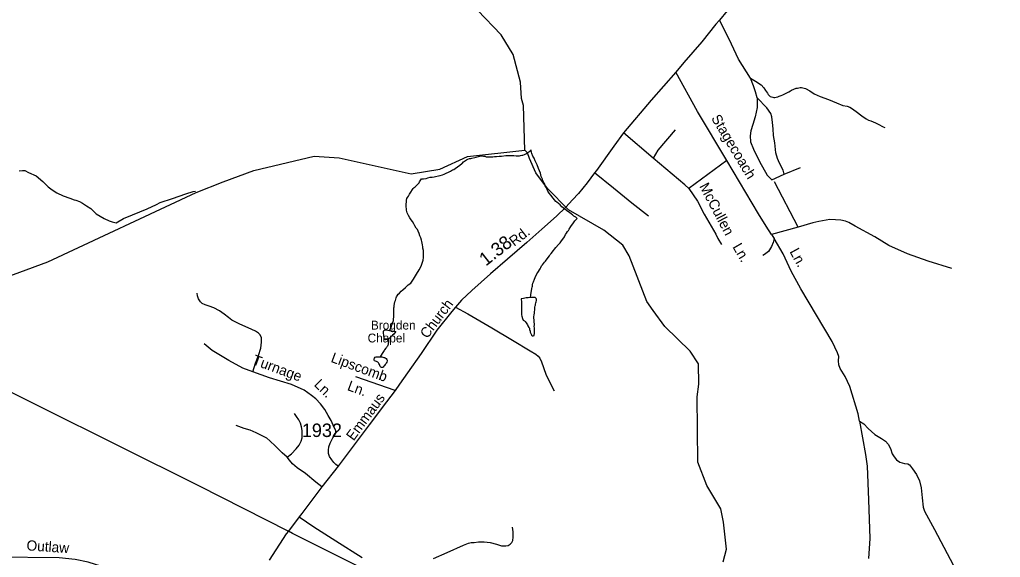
# Model space of a CAD drawing. Extents: x 2206922 to 2357709, y 510027 to 673830.
# Drawn here: x 2296847 to 2305951, y 559014 to 564008 of the extents above; entities that cross this region are included whole.
import ezdxf

# ---------------------------------------------------------------- set-up
doc = ezdxf.new("R2010")
doc.units = 0
for name, color, linetype in [('Exist Cultural Church with Cemetery Label', 7, 'Continuous'), ('Exist Hydrographic Creek Single Shore', 7, 'Continuous'), ('Exist Hydrographic Misc Water Feature', 7, 'Continuous'), ('Exist Road Non-System Type 51', 7, 'Continuous'), ('Exist Road Non-System Type 51 Label', 7, 'Continuous'), ('Exist Road Secondary Mileage Hundredths English Label', 7, 'Continuous'), ('Exist Road Secondary Type 51 Attributed', 7, 'Continuous'), ('Exist Road Secondary Type 51 Label', 7, 'Continuous'), ('Exist Road Secondary Type 51 Number Label', 7, 'Continuous'), ('Exist Utilities Electrical Transmission Line', 7, 'Continuous')]:
    doc.layers.add(name, color=color, linetype=linetype)

msp = doc.modelspace()

# ---------------------------------------------------------------- linework, layer by layer
at = {"layer": 'Exist Hydrographic Creek Single Shore'}
for points in [[(2301537, 562794.8), (2301524.1, 563211.1), (2301506, 563276), (2301497, 563426.5), (2301427.1, 563683), (2301317.2, 563865.6), (2301098.2, 564096.3)], [(2298484, 562402.3), (2298734.5, 562501.6), (2299020.8, 562606.5), (2299580, 562738.8), (2299813.1, 562725.3), (2300481, 562575.1), (2300747.1, 562618.6), (2301004.1, 562737.3), (2301537, 562794.8)], [(2303376.1, 558974), (2303409.1, 559090.1), (2303381.2, 559341.7), (2303355.2, 559465.3), (2303227, 559680), (2303142.1, 559896.5), (2303135.2, 560503.3), (2303151.2, 560622.1), (2303149.1, 560812.3), (2303072.2, 560927.3), (2302837, 561157.4), (2302727.1, 561307.2), (2302668, 561390.1), (2302505, 561813.4), (2302445.2, 561912.7), (2302269, 562053.2), (2301942.2, 562240.3), (2301748.2, 562439.2), (2301639.1, 562585.7), (2301579, 562717.8), (2301562, 562769.6), (2301537, 562794.8)]]:
    msp.add_lwpolyline(points, dxfattribs=at)
at = {"layer": 'Exist Hydrographic Misc Water Feature'}
for points in [[(2300576.1, 562528.5), (2300596, 562528.7), (2300619.6, 562532.9), (2300635.6, 562537), (2300657.5, 562543.4), (2300675.8, 562545.5), (2300694, 562547.6), (2300705.9, 562549.9), (2300735.6, 562555.9), (2300751.8, 562560.4), (2300771.5, 562566.4), (2300787.3, 562572.5), (2300799.4, 562578.8), (2300813.1, 562584.8), (2300821.6, 562588.8), (2300832.8, 562593.2), (2300847, 562601.2), (2300854.8, 562605.3), (2300864.8, 562611.5), (2300876.9, 562617.4), (2300890.7, 562623.9), (2300910.3, 562640), (2300932.3, 562656.1), (2300950.3, 562670.5), (2300954, 562672.3), (2300966.1, 562686.7), (2300976.2, 562692.5), (2300984, 562698.6), (2300995.8, 562707), (2301005.9, 562710.7), (2301021.9, 562717.3), (2301033.6, 562719.1), (2301045.5, 562721.4), (2301071.5, 562727.6), (2301083.8, 562731.8), (2301105.1, 562738), (2301117.4, 562740.2), (2301127.1, 562742.3), (2301141.2, 562742.3), (2301153.1, 562740.4), (2301165.2, 562738.6), (2301177.3, 562734.8), (2301195.8, 562732.8), (2301207.7, 562733), (2301223.5, 562733.1), (2301239.2, 562733.6), (2301253.6, 562735.5), (2301273.5, 562737.8), (2301299.3, 562739.9), (2301319.4, 562740.2), (2301361.3, 562746.8), (2301381.3, 562747), (2301399.2, 562747.2), (2301413.1, 562747.1), (2301432.8, 562745.4), (2301456.8, 562743.8), (2301473, 562741.8), (2301486.9, 562744.1), (2301497.2, 562746.2), (2301508.9, 562748.1), (2301519.1, 562750.2), (2301532.9, 562756.7), (2301545, 562760.5), (2301555, 562766.7), (2301582.7, 562784.9), (2301594.6, 562797.3)], [(2302023.2, 562162.2), (2302009, 562172), (2301991, 562183.7), (2301979.1, 562193.6), (2301968.8, 562201.6), (2301950.8, 562215.2), (2301936.6, 562225.1), (2301880, 562270.5), (2301863.8, 562286.3), (2301833.3, 562312), (2301825.3, 562320.1), (2301811.3, 562333.6), (2301799.2, 562349.6), (2301777.1, 562377.2), (2301762.5, 562397.3), (2301750.6, 562414.9), (2301744.3, 562430.8), (2301736.5, 562447), (2301726.2, 562464.8), (2301718, 562484.7), (2301709.6, 562498.5), (2301703.5, 562514.5), (2301699.4, 562526.4), (2301689.3, 562552.2), (2301681.1, 562582.3), (2301672.5, 562604.3), (2301664.1, 562626.2), (2301652, 562658), (2301641.8, 562677.8), (2301633.6, 562697.7), (2301621.5, 562721.5), (2301611, 562741.2), (2301600.8, 562763.5), (2301596.9, 562775.4), (2301594.6, 562787.1), (2301594.6, 562797.3)], [(2296842.5, 562604.5), (2296874.7, 562606.5), (2296894.6, 562606.7), (2296928.8, 562589.5), (2297000.8, 562557.9), (2297061.7, 562504.6), (2297111.8, 562455.3), (2297147.8, 562427.5), (2297192.1, 562399.7), (2297250.6, 562370.3), (2297312.9, 562351.1), (2297352.7, 562335.4), (2297367, 562331.7), (2297401.3, 562318), (2297429.2, 562304), (2297467.3, 562278.4), (2297507.3, 562252.9), (2297535.8, 562225.1), (2297558.2, 562205.5), (2297630.3, 562162.2), (2297676.5, 562140.7), (2297706.4, 562128.9), (2297742.7, 562119.4)], [(2300281.2, 561119.9), (2300294.8, 561148.3), (2300296.6, 561154.1), (2300299.1, 561158.2), (2300302.8, 561170.2), (2300304.6, 561178.4), (2300318.4, 561212.5), (2300317.9, 561228.3), (2300321.8, 561244.4), (2300321.6, 561258.2), (2300321.8, 561274.4), (2300321.4, 561290.2), (2300321.2, 561306.5), (2300321, 561320.3), (2300321, 561330.5), (2300323.1, 561340.3), (2300324.9, 561354.2), (2300330.3, 561386.3), (2300332.5, 561394.5), (2300334.4, 561400.7), (2300342.1, 561422.6), (2300346, 561432.6), (2300349.7, 561442.5), (2300359.8, 561458.9), (2300371.7, 561468.8), (2300387.5, 561485.1), (2300405.1, 561499.1), (2300428.9, 561521.4), (2300454.5, 561543.5), (2300476.7, 561561.7), (2300490.4, 561577.9), (2300504.1, 561598.1), (2300531.6, 561644.3), (2300555, 561684.5), (2300574.9, 561716.8), (2300592.1, 561775), (2300595.8, 561799.2), (2300595.6, 561819.1), (2300595.4, 561841.1), (2300595, 561863.1), (2300590.9, 561885.1), (2300589, 561898.8), (2300586.6, 561915), (2300582.3, 561930.6), (2300580.4, 561946.7), (2300576.3, 561960.7), (2300569.8, 561982.8), (2300561.8, 562000.7), (2300555.6, 562020.6), (2300545.1, 562044.5), (2300539, 562058.4), (2300528.5, 562072.1), (2300514.8, 562094.1), (2300504.5, 562109.8), (2300492, 562131.6), (2300480.3, 562147.5), (2300467.8, 562167.6), (2300455.7, 562189.3), (2300445.3, 562213.2), (2300437.3, 562239.1), (2300434.8, 562280.9), (2300434.6, 562297.2), (2300436.5, 562313.1), (2300438.1, 562331.1), (2300442.2, 562345.1), (2300447.7, 562355.2), (2300455.7, 562367.4), (2300465.4, 562387.4), (2300471.7, 562397.4), (2300500.9, 562439.6), (2300508.9, 562449.8), (2300518.9, 562456), (2300528.7, 562463.8), (2300542.5, 562480), (2300550.3, 562486.1), (2300554.2, 562492), (2300558.1, 562500.4), (2300576.1, 562528.5)], [(2295560.9, 561493.9), (2296269, 561525.5), (2296643, 561586.8), (2297108.1, 561757.8), (2298484, 562402.3)], [(2297742.7, 562119.4), (2297812.4, 562160), (2297895.9, 562194.4), (2298031.2, 562249.8), (2298116.7, 562290.5), (2298152.6, 562309), (2298264.6, 562346.5), (2298388.4, 562388.7), (2298456.5, 562411.7), (2298480.5, 562415.8)], [(2301589.3, 561427.8), (2301593.4, 561452), (2301602.4, 561511.8), (2301604, 561522.1), (2301606.1, 561532), (2301608.1, 561543.8), (2301611.8, 561560.3), (2301617.4, 561574), (2301627.4, 561598.1), (2301633.6, 561614.2), (2301648.5, 561648.4), (2301656.5, 561660.6), (2301678.3, 561694.6), (2301684.2, 561704.7), (2301692, 561721), (2301699.6, 561730.7), (2301709.8, 561743), (2301717.6, 561755.2), (2301727.9, 561765), (2301735.1, 561775.3), (2301764.8, 561813.8), (2301772.8, 561825.6), (2301780.8, 561835.7), (2301802.5, 561864.1), (2301812.2, 561876), (2301823.8, 561890.1), (2301847.8, 561918.5), (2301863.4, 561936.4), (2301877.2, 561952.6), (2301897.3, 561980.8), (2301903.2, 561990.9), (2301914.9, 562013), (2301922.9, 562025.2), (2301932.5, 562039.1), (2301940.5, 562049.3), (2301948.5, 562061.5), (2301963.9, 562085.5), (2301987.9, 562121.7), (2302001.4, 562139.9), (2302023.2, 562162.2)], [(2301589.3, 561427.8), (2301583.5, 561425.9), (2301567.3, 561423.8), (2301547.4, 561423.6), (2301535.5, 561421.3), (2301525.3, 561419.2), (2301503.4, 561415.2), (2301504, 561385.1), (2301503.8, 561368.9), (2301504, 561357.1), (2301504.4, 561339.3), (2301504.2, 561323.1), (2301504.4, 561311.3), (2301504.6, 561297), (2301504.8, 561290.9), (2301504.8, 561283.2), (2301504.8, 561277.1), (2301505, 561271), (2301504.8, 561265), (2301507, 561253.2), (2301513.6, 561233.2), (2301521.6, 561217.5), (2301525.5, 561213.6), (2301531.7, 561209.4), (2301539.6, 561203.4), (2301547.8, 561191.6), (2301553.8, 561181.7), (2301560.2, 561173.9), (2301563.8, 561165.6), (2301574.5, 561149.8), (2301578.2, 561142), (2301578.4, 561137.9), (2301580.5, 561129.9), (2301584.6, 561115.9), (2301586.8, 561104.2), (2301588.9, 561098.2), (2301591.1, 561094.2), (2301596.9, 561080.4), (2301599.3, 561076.4), (2301604.9, 561072.3), (2301613.1, 561070.2), (2301623.1, 561074.4), (2301626.8, 561094.5), (2301626.8, 561106.7), (2301626.6, 561120.5), (2301626.2, 561136.4), (2301626.2, 561146.5), (2301623.9, 561158.6), (2301625.8, 561174.5), (2301623.5, 561206.5), (2301621.5, 561220.2), (2301621.3, 561236.5), (2301620.8, 561250.3), (2301623.3, 561264.2), (2301624.9, 561284.2), (2301628.4, 561320.5), (2301630.1, 561338.5), (2301632.1, 561348.4), (2301634.4, 561356.6), (2301635.6, 561364.5), (2301639.7, 561376.4), (2301641.6, 561386.7), (2301643.8, 561400.6), (2301643.6, 561406.7), (2301643.4, 561410.4), (2301641.4, 561418.4), (2301633.4, 561426.5), (2301621.3, 561428.3), (2301609.4, 561426), (2301597.3, 561427.8), (2301589.3, 561427.8)], [(2300270, 561040.1), (2300258.3, 561037.8), (2300244.3, 561033.8), (2300232, 561041.8), (2300230.2, 561055.4), (2300227.7, 561071.6), (2300227.9, 561077.7), (2300225.3, 561095.5), (2300223.4, 561107.5), (2300225.3, 561115.4), (2300227.1, 561119.5), (2300235.3, 561125.6), (2300247.4, 561125.8), (2300263.6, 561123.8), (2300281.2, 561119.9)], [(2300281.2, 561119.9), (2300289.2, 561119.9), (2300301.3, 561118.1), (2300339.3, 561110.8), (2300325.5, 561094.6), (2300319.4, 561086.6), (2300307.9, 561076.5), (2300303.8, 561072.3), (2300295.8, 561064.2), (2300290.1, 561058.2), (2300284.1, 561050.1), (2300274.1, 561043.9), (2300270, 561040.1)], [(2300270, 561040.1), (2300272, 561024), (2300272.2, 561017.8), (2300268.5, 560998.2), (2300266.9, 560989.9), (2300265, 560984.1), (2300260.5, 560975.8), (2300256.6, 560969.9), (2300251.1, 560961.9), (2300244.9, 560955.9), (2300233.3, 560941.4), (2300229.4, 560935.5), (2300211.3, 560907.4), (2300194.1, 560875.1)], [(2300194.1, 560875.1), (2300208.2, 560875.4), (2300218.1, 560873.5), (2300226.3, 560871.5), (2300234.1, 560869.5), (2300240.2, 560865.7), (2300248, 560859.7), (2300254.4, 560851.8), (2300258.1, 560846), (2300258.1, 560837.9), (2300254.8, 560827.9), (2300250.5, 560818), (2300244.5, 560810), (2300240.8, 560803.6), (2300234.9, 560795.6), (2300228.7, 560789.6), (2300221, 560781.5), (2300214.8, 560777.5), (2300205.2, 560777.4), (2300199, 560781.5), (2300192.7, 560787.4), (2300189, 560795.2), (2300186.7, 560805.2), (2300182.4, 560815.2), (2300178.3, 560821.1), (2300172.6, 560826.9), (2300160.3, 560832.8), (2300150.4, 560836.7), (2300140.4, 560840.6), (2300138.5, 560844.6), (2300138.5, 560854.7), (2300140.2, 560864.6), (2300146.1, 560872.6), (2300156.2, 560876.8), (2300168.1, 560877), (2300177.9, 560875.1), (2300186.1, 560875.1), (2300194.1, 560875.1)]]:
    msp.add_lwpolyline(points, dxfattribs=at)
at = {"layer": 'Exist Road Non-System Type 51'}
for p, q in [((2302728.8, 562719.7), (2302453.3, 562955.8)), ((2303411.4, 562700.7), (2303058.2, 562439.3)), ((2303943.1, 562573.3), (2304094.8, 562634)), ((2304074.8, 562080), (2303854.3, 562501.4)), ((2304074.8, 562080), (2303824.7, 562011.4)), ((2303824.7, 562011.4), (2303850.1, 561975)), ((2300332.7, 560564.7), (2299966, 560690.4))]:
    msp.add_line(p, q, dxfattribs=at)
for points in [[(2303631.7, 563463.7), (2303520.4, 563641.8), (2303433.5, 563825.9), (2303342, 564002.9)], [(2303411.4, 562700.7), (2303139, 563155.5), (2302939.4, 563519.9)], [(2303694.4, 563281.6), (2303676.2, 563336.2), (2303658, 563392.9), (2303631.7, 563463.7)], [(2303631.7, 563463.7), (2303678.2, 563437.4), (2303730.8, 563401), (2303755, 563374.7), (2303769.2, 563350.4), (2303779.3, 563336.2), (2303787.4, 563324.1), (2303795.5, 563311.9), (2303803.6, 563303.8), (2303811.7, 563295.7), (2303813.7, 563293.7), (2303825.8, 563289.7), (2303838, 563287.7), (2303848.1, 563285.6), (2303858.2, 563285.6), (2303868.3, 563287.7), (2303884.5, 563291.7), (2303898.6, 563295.7), (2303916.8, 563301.8), (2303931, 563307.9), (2303973.5, 563330.1), (2303987.6, 563338.2), (2304003.8, 563346.3), (2304011.9, 563352.4), (2304034.1, 563362.5), (2304056.4, 563370.6), (2304068.5, 563372.6), (2304090.8, 563376.7), (2304102.9, 563376.7), (2304141.3, 563368.6), (2304181.8, 563346.3), (2304222.2, 563320), (2304278.8, 563293.7), (2304355.7, 563267.4), (2304428.5, 563235), (2304489.2, 563210.8), (2304529.6, 563202.7), (2304551.9, 563194.6), (2304570.1, 563184.5), (2304612.5, 563154.1), (2304663.1, 563113.6), (2304703.6, 563085.3), (2304727.8, 563075.2), (2304748.1, 563069.1), (2304792.5, 563048.9), (2304816.8, 563036.7), (2304861.3, 563012.4), (2304877.5, 563004.4)], [(2303694.4, 563281.6), (2303692.3, 563192.5), (2303674.1, 563103.5), (2303651.9, 563034.7), (2303633.7, 562976), (2303627.6, 562929.5), (2303631.7, 562872.8), (2303660, 562806), (2303714.6, 562690.7), (2303785.4, 562563.2), (2303829.9, 562518.7), (2303943.1, 562573.3)], [(2303943.1, 562573.3), (2303933, 562609.8), (2303900.7, 562674.5), (2303880.4, 562717), (2303866.3, 562771.6), (2303856.2, 562862.7), (2303844, 562931.5), (2303842, 562992.2), (2303833.9, 563050.9), (2303829.9, 563103.5), (2303819.8, 563135.9), (2303781.3, 563188.5), (2303694.4, 563281.6)], [(2302931.5, 562984.4), (2302770, 562795.8), (2302728.8, 562719.7)], [(2303058.2, 562439.3), (2303021.8, 562474.1), (2302728.8, 562719.7)], [(2303824.7, 562011.4), (2303777.2, 562089.1), (2303704.4, 562204.8), (2303411.4, 562700.7)], [(2302684.5, 562181), (2302529.3, 562303), (2302358.2, 562444), (2302183.7, 562583.7)], [(2303058.2, 562439.3), (2303140.6, 562320.4), (2303202.3, 562200), (2303310, 562016.2), (2303329, 561975), (2303362.3, 561917.9)], [(2305498.4, 561697.1), (2305279.9, 561765.9), (2305087.8, 561832.7), (2304915.9, 561909.6), (2304785.3, 561991.7), (2304602.5, 562089.7), (2304544.1, 562123), (2304514.1, 562134.7), (2304469.9, 562144.2), (2304419.9, 562147.5), (2304366, 562151), (2304266.1, 562131.9), (2304210.3, 562121.5), (2304074.8, 562080)], [(2303850.1, 561975), (2303842.1, 561937), (2303826.9, 561901.3), (2303799.4, 561855), (2303761.7, 561826.7), (2303745.9, 561818.4)], [(2304641.8, 560279.1), (2304629.1, 560346.8), (2304553.2, 560601.2), (2304508.9, 560694.7), (2304464.5, 560769.1), (2304451.9, 560802.4), (2304448.7, 560838.9), (2304451.9, 560878.5), (2304439.2, 560913.3), (2304388.5, 561017.9), (2304098.7, 561507.5), (2304008.4, 561670.8), (2303934, 561832.4), (2303850.1, 561975)], [(2299012.4, 560736), (2299037.4, 560816.1), (2299065.2, 560889.5), (2299085.5, 560957.8), (2299093.1, 561013.5), (2299090.5, 561051.5), (2299080.4, 561081.9), (2299065.2, 561097.1), (2299037.4, 561114.8), (2298969.1, 561145.2), (2298890.7, 561180.6), (2298847.7, 561200.9), (2298817.3, 561216), (2298784.4, 561241.4), (2298743.9, 561271.7), (2298703.4, 561302.1), (2298650.3, 561330), (2298604.8, 561345.2), (2298569.3, 561357.8), (2298541.5, 561370.5), (2298526.3, 561385.7), (2298508.6, 561413.5), (2298498.5, 561441.3), (2298496, 561466.7)], [(2300893.8, 561338.7), (2301006.6, 561274.2), (2301231, 561144.7), (2301423.2, 561031.4), (2301585, 560932.2), (2301639.6, 560901.9), (2301659.8, 560881.6), (2301674, 560863.4), (2301692.2, 560829), (2301730.6, 560715.7), (2301769, 560636.8), (2301807.4, 560559.9)], [(2299012.4, 560736), (2298918.3, 560769.6), (2298788.5, 560842.5), (2298634.9, 560934.4), (2298559.5, 560997.2)], [(2299803.6, 559860.1), (2299783, 559877.5), (2299764, 559894.9), (2299743.4, 559920.3), (2299724.4, 559950.4), (2299714.9, 559978.9), (2299713.3, 560009), (2299716.5, 560040.7), (2299730.8, 560074), (2299754.5, 560123.1), (2299781.4, 560165.9), (2299781.4, 560188.1), (2299757.7, 560240.4), (2299737.1, 560286.3), (2299711.8, 560332.3), (2299678.5, 560387.7), (2299638.9, 560438.4), (2299597.7, 560486), (2299555, 560517.7), (2299488.5, 560566.8), (2299371.1, 560620.1), (2299167, 560680.9), (2299012.4, 560736)], [(2299330.1, 559944), (2299369.7, 559975.7), (2299414, 560021.7), (2299441, 560056.5), (2299460, 560093), (2299467.9, 560123.1), (2299469.5, 560158), (2299467.9, 560192.8), (2299464.7, 560227.7), (2299453.6, 560261), (2299437.8, 560292.6), (2299415.6, 560321.2), (2299398.2, 560351.3)], [(2304641.8, 560279.1), (2304682, 560253.5), (2304722.5, 560211.9), (2304785.1, 560154.6), (2304845.5, 560119.3), (2304883.7, 560093.8), (2304908.1, 560064), (2304930.5, 560024.3), (2304947, 559974.5), (2304965.3, 559946.7), (2304985.6, 559918.9), (2305015.8, 559899.3), (2305062, 559885.7), (2305091.9, 559882), (2305107.9, 559872.2), (2305134.4, 559836.5), (2305170.9, 559784.9), (2305199.5, 559725.3), (2305216.1, 559659.5), (2305223.3, 559565.6), (2305234.2, 559479.8), (2305246.5, 559441.9), (2305340.4, 559273.1), (2305950.6, 558112.2)], [(2304641.8, 560279.1), (2304697.2, 559967.8), (2304714.3, 559859.9), (2304725.7, 559548.3), (2304737.6, 559190.7), (2304725.5, 559004.6)], [(2299330.1, 559944), (2299284.2, 559985.2), (2299222.4, 560047), (2299170.1, 560094.6), (2299140.1, 560119.9), (2299098.9, 560143.7), (2299043.5, 560170.6), (2298988, 560194.4), (2298931, 560211.8), (2298858.2, 560237.2)], [(2299651.6, 559669.9), (2299596.2, 559712.7), (2299499.6, 559791.9), (2299423.5, 559845.8), (2299380.8, 559883.8), (2299352.3, 559915.5), (2299330.1, 559944)], [(2299441, 559389.1), (2299578.7, 559297.2), (2299781, 559167.7), (2300027.7, 559011.9)], [(2300689, 559003.8), (2300814.4, 559058.4), (2300968.1, 559127.2), (2301014.6, 559145.4), (2301038.9, 559151.5), (2301065.2, 559151.5), (2301107.7, 559157.6), (2301160.3, 559157.6), (2301214.9, 559153.5), (2301273.5, 559135.3), (2301320, 559121.1), (2301344.3, 559121.1), (2301360.5, 559121.1), (2301380.7, 559125.2), (2301398.9, 559135.3), (2301415.1, 559151.5), (2301425.2, 559171.7), (2301429.2, 559200.1), (2301427.2, 559250.6), (2301423.2, 559293.1)]]:
    msp.add_lwpolyline(points, dxfattribs=at)
at = {"layer": 'Exist Road Secondary Type 51 Attributed'}
for points in [[(2303415.5, 564089.8), (2303342, 564002.9), (2303310, 563965.2), (2303180.2, 563802), (2303012.3, 563608.7), (2302939.4, 563519.9), (2302708.2, 563258.5), (2302453.3, 562955.8), (2302363, 562832.2), (2302201.4, 562607.2), (2302183.7, 562583.7), (2302114.3, 562491.6), (2302033.6, 562393.3), (2301979.7, 562334.7), (2301918, 562265), (2301829.3, 562181), (2301693.1, 562062.1), (2301553.7, 561938.5), (2301374.8, 561783.3), (2301218, 561647), (2301043.8, 561493.3), (2300948.8, 561401.4), (2300893.8, 561338.7), (2300858.5, 561298.4), (2300720.7, 561122.5), (2300575, 560908.6), (2300446.7, 560726.3), (2300373.9, 560623.4), (2300332.7, 560564.7), (2300251.9, 560457), (2300090.4, 560244.6), (2299803.6, 559860.1), (2299651.6, 559669.9), (2299466.3, 559422.7), (2299441, 559389.1), (2299341.4, 559256.6), (2299322.2, 559231), (2299162.2, 558987)], [(2298859.7, 558470.4), (2298505, 558600.3), (2298291.2, 558676.4), (2297727.2, 558892.3), (2297482.7, 558970), (2297362.4, 558994.9), (2297214.4, 559009.5), (2296625.4, 559016.5), (2296290.5, 559040.6), (2295898.2, 559068.9)]]:
    msp.add_lwpolyline(points, dxfattribs=at)
at = {"layer": 'Exist Utilities Electrical Transmission Line'}
for points in [[(2296290.5, 560784.4), (2298507.6, 559681.3), (2299341.4, 559256.6)], [(2305471, 556194.3), (2303003.5, 557428.9), (2300855, 558499.2), (2299379.9, 559237), (2299341.4, 559256.6)]]:
    msp.add_lwpolyline(points, dxfattribs=at)

# ---------------------------------------------------------------- texts
at = {"layer": 'Exist Cultural Church with Cemetery Label'}
for s, p in [('Brogden', (2300107.6, 561129.6)), ('Chapel', (2300077, 561009.9))]:
    msp.add_text(s, height=82.02, dxfattribs=at).set_placement(p)
at = {"layer": 'Exist Road Non-System Type 51 Label'}
for s, rotation, p in [('Stagecoach', 300.93246, (2303262.8, 563092.2)), ('McCullen', 297.78044, (2303153.2, 562461.3)), ('Ln.', 300.02821, (2303461.1, 561898)), ('Ln.', 298.59864, (2303991, 561854)), ('Lipscomb', 339.65674, (2299728.7, 560830.9)), ('Turnage', 339.77835, (2299001.1, 560808.8)), ('Ln.', 315.61611, (2299573, 560611.9)), ('Ln.', 339.65674, (2299881.4, 560569.1))]:
    msp.add_text(s, height=95, rotation=rotation, dxfattribs=at).set_placement(p)
at = {"layer": 'Exist Road Secondary Mileage Hundredths English Label'}
msp.add_text('1.38', height=125, rotation=38.32547, dxfattribs=at).set_placement((2301174.1, 561713.4))
at = {"layer": 'Exist Road Secondary Type 51 Label'}
for s, rotation, p in [('Rd.', 38.02847, (2301437.3, 561897.6)), ('Church', 52.88477, (2300630.8, 561039.6)), ('Emmaus', 53.56773, (2299946.3, 560090.1)), ('Outlaw', 356.06949, (2296908.3, 559079.8))]:
    msp.add_text(s, height=95, rotation=rotation, dxfattribs=at).set_placement(p)
at = {"layer": 'Exist Road Secondary Type 51 Number Label'}
msp.add_text('1932', height=125, dxfattribs=at).set_placement((2299466.4, 560131.7))

doc.saveas('drawing.dxf')
